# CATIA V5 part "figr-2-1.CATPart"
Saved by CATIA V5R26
Part number: figr-2-1
Bounding box of the stored display mesh (mm): x 0 to 10, y -99.811 to 99.811, z -49.833 to 49.833
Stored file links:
  D:\_Deepak\CATIA\CATIA V5-6R2016_Deepak\Resources\Part files\Partfiles\c02_catia_v5_6r2016_prt\figr-2-1.CATPart
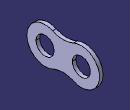
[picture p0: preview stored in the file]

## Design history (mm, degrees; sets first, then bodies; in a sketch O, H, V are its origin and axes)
Body1 (main body)
  Sketch1 on yz-plane, origin (0, 0, 0), H (0, 1, 0), V (0, 0, 1)
    arc A1 centre (50, 0) radius 50 from (29.1667, -45.453) to (29.1666, 45.4529) ccw
    point P1 (50, 0)
    arc A2 centre (-50, 0) radius 50 from (-29.1666, 45.4529) to (-29.1667, -45.453) ccw
    point P2 (-50, 0)
    arc A3 centre (0, 109.0871) radius 70 from (-29.1666, 45.4529) to (29.1667, 45.453) ccw
    point P4 (-29.1666, 45.4529)
    point P5 (0, 39.0871)
    point P6 (29.1667, 45.453)
    point P7 (29.1667, -45.453)
    point P8 (-29.1666, -45.4529)
    arc A4 centre (0, -109.0871) radius 70 from (-29.1666, -45.4529) to (29.1667, -45.453) cw
    point P10 (-29.1667, -45.453)
    point P11 (-29.1666, 45.4529)
    point P12 (29.1666, 45.4529)
    point P13 (29.1667, -45.453)
    circle A5 centre (50, 0) radius 25
    circle A6 centre (-50, 0) radius 25
    distance P1 P2 = 100
    radius A1 = 50
    radius A2 = 50
    distance O P2 = 50
    radius A5 = 25
    radius A6 = 25
    radius A3 = 70
    coincidence: P1 H, P2 H, P4 A2, A3 P5, P5 V, P6 A1, A4 P10, A3 P11, A3 P12, A4 P13
    tangency: A3 A1, A3 A2
    symmetry: P6 P7 H, P4 P8 H, A3 A4 H
  Pad1: profile Sketch1, direction (1, 0, 0), length 10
